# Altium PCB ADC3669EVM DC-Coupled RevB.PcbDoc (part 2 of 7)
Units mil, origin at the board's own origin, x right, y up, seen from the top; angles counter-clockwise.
Board outline 5000 x 2716.54 mil, 12 copper layers (Top Layer, L2 GND, L3 SIG, L4 GND, L5 PWR, L6 GND, L7 GND, L8 PWR, L9 GND, L10 PWR, L11 GND, Bottom Layer), stack 61 mil thick; 546 components, 341 nets, 2088 pads, 1256 vias.
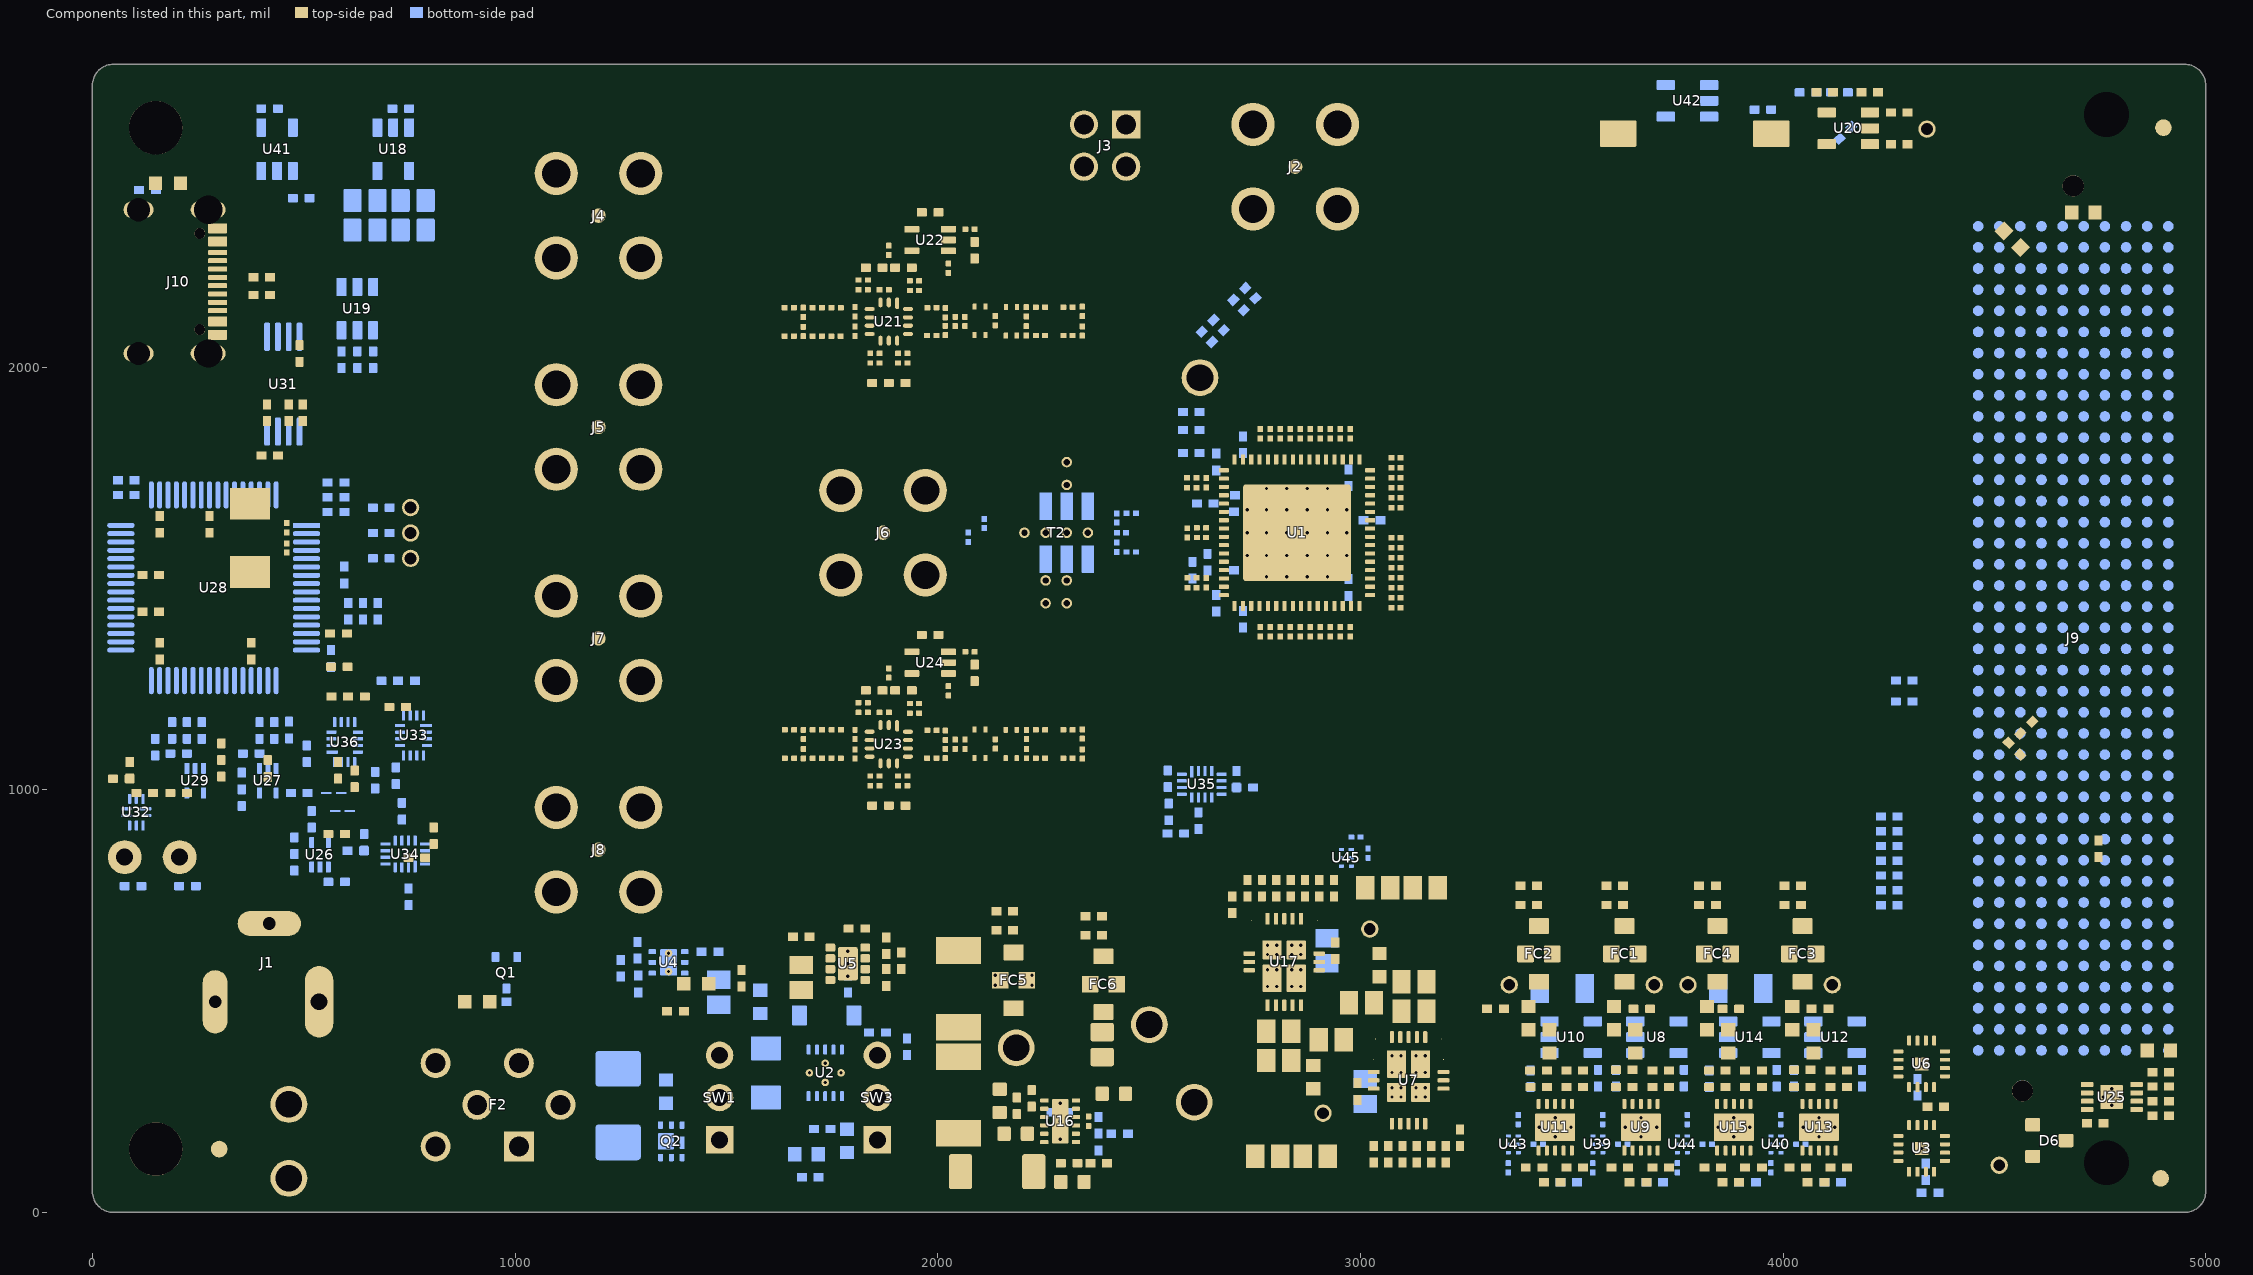
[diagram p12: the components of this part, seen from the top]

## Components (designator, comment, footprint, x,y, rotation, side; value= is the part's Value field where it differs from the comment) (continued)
R220 "ERJ-2GE0R00X" 0402L#2 188.64,1140.31 r270 bottom value="0 Ω"
R221 "ERJ-H2RF1000X" 0402L#2 148.64,1100.94 r90 bottom value="100 Ω"
R222 "ERJ-2GE0R00X" 0402L#1 138.45,1421.08 r0 top value="0 Ω"
R224 "ERJ-2RKF10R0X" 0402L#1 582.21,1369.71 r0 top value="10 Ω"
R225 "ERJ-2RKF1001X" 0402L#1 130.34,2419.03 r0 bottom value="1 kΩ"
R227 "ERJ-2RKF10R0X" 0402L#1 400.5,2212.28 r0 top value="10 Ω"
R229 "ERJ-2RKF10R0X" 0402L#1 400.5,2170.78 r0 top value="10 Ω"
R240 "ERA-2ARB123X" 0402L#1 595.94,1508.27 r90 bottom value="12 kΩ"
R241 "ERJ-2RKF1002X" 0402L#1 464.48,1892.15 r90 top value="10 kΩ"
R242 "ERJ-2RKF1002X" 0402L#1 413.3,1892.15 r90 top value="10 kΩ"
R243 "ERJ-2RKF1002X" 0402L#1 498.07,1892.15 r90 top value="10 kΩ"
R244 "ERJ-2RKF2201X" 0402L#1 419.87,1791.02 r0 top value="2.2 kΩ"
R245 "ERJ-H2RF4701X" 0402L#2 225.01,772.13 r0 bottom value="4.7 kΩ"
R246 "ERJ-H2RF4701X" 0402L#2 96.14,772.13 r0 bottom value="4.7 kΩ"
R247 "ERJ-2GEJ472X" 0402L#1 88.25,1045.83 r90 top value="4.7 kΩ"
R248 "ERJ-2GE0R00X" 0402L#2 68.57,1026.14 r0 top value="0 Ω"
R249 "ERJ-H2RF4701X" 0402L#2 683.31,1607.55 r180 bottom value="4.7 kΩ"
R250 "ERJ-H2RF4701X" 0402L#2 4133.43,2650 r0 bottom value="4.7 kΩ"
R251 "ERJ-H2RF4701X" 0402L#2 683.31,1547.55 r0 bottom value="4.7 kΩ"
R252 "ERJ-H2RF4701X" 0402L#2 683.31,1667.55 r0 bottom value="4.7 kΩ"
R253 "ERJ-H2RF4701X" 0402L#2 4059.06,2650 r0 bottom value="4.7 kΩ"
R254 "ERJ-H2RF4701X" 0402L#2 1927.43,392.06 r90 bottom value="4.7 kΩ"
R255 "ERJ-2GEJ472X" 0402L#1 743.15,1257.76 r0 bottom value="4.7 kΩ"
R256 "ERJ-2GE0R00X" 0402L#2 703.78,1257.76 r0 bottom value="0 Ω"
R257 "ERJ-H2RF4701X" 0402L#2 2706.9,1024.95 r90 bottom value="4.7 kΩ"
R258 "ERJ-2GEJ472X" 0402L#1 623.26,855.94 r180 bottom value="4.7 kΩ"
R259 "ERA-2AED102X" 0402L#2 732.31,949.25 r90 bottom value="1 kΩ"
R260 "ERJ-H2RF4701X" 0402L#2 2563.35,896.64 r0 bottom value="4.7 kΩ"
R261 "ERJ-H2RF4701X" 0402L#2 2616.78,926.95 r90 bottom value="4.7 kΩ"
R262 "ERJ-2GE0R00X" 0402L#2 642.94,875.63 r270 bottom value="0 Ω"
R263 "ERJ-2GE0R00X" 0402L#2 2726.59,1005.26 r180 bottom value="0 Ω"
R264 "ERJ-2GEJ472X" 0402L#1 585.51,1220.56 r180 top value="4.7 kΩ"
R266 "ERA-2AED102X" 0402L#2 718,1033.31 r270 bottom value="1 kΩ"
R267 "ERJ-2GE0R00X" 0402L#2 624.88,1220.56 r180 top value="0 Ω"
R272 "ERJ-1GN0R00C" 0201#2 3820.6,161.38 r0 bottom value="0 Ω"
R273 "ERA-2AEB202X" 0402L#2 589.45,2017.56 r270 bottom value="2 kΩ"
R274 "ERA-2AEB202X" 0402L#2 626.85,2017.56 r270 bottom value="2 kΩ"
R275 "ERA-2AEB202X" 0402L#2 664.25,2017.56 r270 bottom value="2 kΩ"
SW1 "cmp00353" 450301014042 1484,271.9 r270 top
SW2 "FSMSM" FSMSM 3790.75,2552.4 r180 top
SW3 "450301014042" 450301014042 1857.15,271.9 r270 top
T2 "TCM2-33WX+" "DB1627 - Vias 1,2,5" 2305.23,1608.27 r0 bottom
TP1 "5010" Keystone5010 465,255.74 r90 top
TP2 "cmp00041" Keystone5011 2606.78,260.81 r90 top
TP3 "5125" Keystone5125 465,80.74 r90 top
TP4 "cmp00043" Keystone5013 2620.51,1975 r90 top
TP5 "cmp00058" Keystone5117 206.45,840.61 r90 top
TP6 "cmp00058" Keystone5117 76.45,840.61 r90 top
TP8 "5127" Keystone5127 2500.85,444.63 r90 top
TP9 "5012" Keystone5012 2185.67,389.33 r90 top
U1 "ADC3669RTD" RTD0064L 2850,1608.27 r270 top locked
U2 "TPS259261DRC" DRC0010J 1733.87,330.21 r90 bottom
U3 "ADS1119IRTER" RTE0016D 4327.8,151.44 r270 top
U4 "TPS7A2501DRVR" DRV0006A 1363.17,591.58 r0 bottom
U5 "TPS82140SILR" SIL0008D 1787.18,588.32 r0 top
U6 "ADS1119IRTER" RTE0016D 4327.8,351.44 r270 top
U7 "TPSM82913RDUR" RDU0028A 3113.94,312.61 r180 top
U8 "INA180B1IDBVR" DBV0005A 3701.57,414.63 r0 bottom
U9 "TPS7A9401DSC" DSC0010 3663.77,201.64 r90 top
U10 "INA180B1IDBVR" DBV0005A 3498.64,414.63 r0 bottom
U11 "TPS7A9401DSC" DSC0010 3460.84,201.64 r90 top
U12 "INA180B1IDBVR" DBV0005A 4122.88,414.63 r0 bottom
U13 "TPS7A9401DSC" DSC0010 4085.08,201.64 r90 top
U14 "INA180B1IDBVR" DBV0005A 3921.32,414.63 r0 bottom
U15 "TPS7A9401DSC" DSC0010 3883.53,201.64 r90 top
U16 "LM27762DSS" DSS0012B 2289.55,215.75 r0 top
U17 "TPSM82913RDUR" RDU0028A 2819.69,592.56 r0 top
U18 "TPS70950DBV" DBV0005A 711.75,2515.35 r270 bottom
U19 "LM3880MFE-1AD" DBV0006A 626.85,2138.42 r270 bottom
U20 "TPS3125J18DBVR" DBV0005A 4154.29,2565 r180 top
U21 "LMH5401IRMSR" RMS0014A 1884.25,2107.84 r270 top
U22 "OPA376AIDCKR" DCK0005A 1981.93,2300.71 r180 top
U23 "LMH5401IRMSR" RMS0014A 1884.25,1107.84 r270 top
U24 "OPA376AIDCKR" DCK0005A 1981.93,1300.71 r180 top
U25 "24LC64FT-I/MNY" TDFN8 4777.42,273.14 r180 top
U26 "SN74AUP1G126DRL" DRL0005A 538.52,846.24 r90 bottom
U27 "SN74LVC1G126DRL" DRL0005A 415.07,1021.5 r270 bottom
U28 "FT4232HL-REEL" LQFP64-MFG 287.11,1477.98 r180 bottom locked
U29 "SN74LVC1G125DRL" DRL0005A 243.33,1021.5 r270 bottom
U31 "93LC46B-I/ST" TSSOP-8 451.68,1959.67 r90 bottom
U32 "TMUX154ERSW" RSW0010A 104,947 r180 bottom
U33 "SN74CBTLV3257RSV" RSV0016A 759.87,1128.5 r180 bottom
U34 "SN74AVC4T774RSV" RSV0016A 740.19,848.07 r90 bottom
U35 "SN74AVC4T774RSV" RSV0016A 2624.66,1013.14 r270 bottom
U36 "SN74AVC4T774RSV" RSV0016A 596.88,1112.76 r0 bottom
U39 "SN74AUP1G08DRY" DRY0006A 3561.73,161.29 r180 bottom
U40 "SN74AUP1G08DRY" DRY0006A 3983.04,161.29 r180 bottom
U41 "TPS3847108DBVR" DBV0005A 436.95,2515.35 r90 bottom
U42 "SN74LVC1G04DBV" DBV0005A 3773.82,2630 r180 bottom
U43 "SN74AUP1G08DRY" DRY0006A 3361.73,161.29 r180 bottom
U44 "SN74AUP1G08DRY" DRY0006A 3761.73,161.29 r180 bottom
U45 "SN74AUP1G08DRY" DRY0006A 2966.68,839.08 r180 bottom
Y1 "ABM3-12.000MHZ-D2Y-T" XTAL_ABM3 372.69,1596.09 r270 top
ZZ1 "This Assembly Note is for PCB labels only. Put sticker on top of board." AssemblyNoteLabel 382.34,5272.5 r0 top
ZZ2 "These assemblies are ESD sensitive, ESD precautions shall be observed." AssemblyNote 382.34,5422.11 r0 top
ZZ3 "These assemblies must be clean and free from flux and all contaminants. Use of no clean flux is not acceptable." AssemblyNote 382.34,5571.73 r0 top
ZZ4 "These assemblies must comply with workmanship standards IPC-A-610 Class 2, unless otherwise specified." AssemblyNote 382.34,5720.36 r0 top

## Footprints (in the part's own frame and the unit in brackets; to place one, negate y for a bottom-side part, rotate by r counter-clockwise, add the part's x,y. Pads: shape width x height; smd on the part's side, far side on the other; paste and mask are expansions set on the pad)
0201#1 [mm] "Data from Kemet datasheet CC101_COM dated 7/28/11"
  rect 0.36x0.32 smd mask+0.048: 1(-0.28,0) 2(0.28,0)
  body extent -0.31,-0.16 0.31,0.16, height 0.26
0201#2 [mm] "Data from Kemet datasheet CC101_COM dated 7/28/11"
  rrect20% 0.36x0.32 smd mask+0.051: 1(-0.28,0) 2(0.28,0)
  body extent -0.3,-0.15 0.3,0.15, height 0.23
0201_cap#1 [mm] "Data from Kemet datasheet CC101_COM dated 7/28/11"
  rrect20% 0.36x0.32 smd mask+0.051: 1(-0.28,0) 2(0.28,0)
  body extent -0.31,-0.16 0.31,0.16, height 0.26
0201_cap#2 [mm] "Data from Kemet datasheet CC101_COM dated 7/28/11"
  rect 0.36x0.32 smd mask+0.048: 1(-0.28,0) 2(0.28,0)
  body extent -0.31,-0.16 0.31,0.16, height 0.26
0402L#1 [mm] "0402 from SM-752 data"
  rect 0.6x0.5 smd: 1(-0.5,0) 2(0.5,0)
  body extent -0.55,-0.3 0.55,0.3, height 0.6
0402L#2 [mm] "0402 from SM-752 data"
  rrect20% 0.6x0.5 smd mask+0.051: 1(-0.5,0) 2(0.5,0)
  body extent -0.55,-0.3 0.55,0.3, height 0.6
0402L_cap#1 [mm] "0402 from SM-752 data"
  rect 0.6x0.5 smd: 1(-0.5,0) 2(0.5,0)
  body extent -0.55,-0.3 0.55,0.3, height 0.6
0402L_cap#2 [mm] "0402 from SM-752 data"
  rrect20% 0.6x0.5 smd mask+0.051: 1(-0.5,0) 2(0.5,0)
  body extent -0.55,-0.3 0.55,0.3, height 0.6
0603L [mm] "0603 from SM-752 data"
  rect 0.8x0.85 smd: 1(-0.7,0) 2(0.7,0)
  silkscreen extent -0.07,-0.33 0.07,0.33, body extent -0.87,-0.47 0.87,0.47, height 1
0603L_cap#1 [mm] "0603 from SM-752 data"
  rect 0.8x0.85 smd: 1(-0.7,0) 2(0.7,0)
  silkscreen extent -0.07,-0.33 0.07,0.33, body extent -0.87,-0.47 0.87,0.47, height 1
0603L_cap#2 [mm] "0603 from SM-752 data"
  rrect20% 0.8x0.85 smd: 1(-0.7,0) 2(0.7,0)
  silkscreen extent -0.07,-0.33 0.07,0.33, body extent -0.87,-0.47 0.87,0.47, height 1
0805L [mm] "0805 from SM-752 data"
  rrect20% 1.1x1.4 smd: 1(-0.75,0) 2(0.75,0)
  body extent -1.1,-0.72 1.1,0.72, height 1.45
0805L_cap#1 [mm] "0805 from SM-752 data"
  rect 1.1x1.4 smd: 1(-0.75,0) 2(0.75,0)
  body extent -1.1,-0.72 1.1,0.72, height 1.45
0805L_cap#2 [mm] "0805 from SM-752 data"
  rrect20% 1.1x1.4 smd: 1(-0.75,0) 2(0.75,0)
  body extent -1.1,-0.72 1.1,0.72, height 1.45
1206L [mm] "1206 from SM-752 data"
  rect 1.1x1.75 smd: 1(-1.35,0) 2(1.35,0)
  silkscreen extent -0.4,-0.77 0.4,0.77, body extent -1.7,-0.9 1.7,0.9, height 1.35
2010 [mm] "Chip Capacitor, Body 5.08x2.54mm, IPC Medium Density"
  rect 1.6x2.7 smd: 1(-2.3,0) 2(2.3,0)
  body extent -2.73,-1.45 2.73,1.45, height 1.66
026011C [mm] "CoilCraft 026011C Series Inductors"
  rrect20% 0.25x0.36 smd mask+0.05: 1(-0.33,0) 2(0.33,0)
  body extent -0.38,-0.16 0.38,0.17, height 0.56
450301014042 [mm]
  round 1.65 hole 1.016: 1(0,0) 2(-2.54,0)
  rect 1.65x1.65 hole 1.016: 3(2.54,0)
  silkscreen extent -4.25,-1.3 4.25,1.6, body extent -4.98,-1.25 5.02,1.25, height 5.9
AssemblyNote [mil] "Assembly Note"
AssemblyNoteLabel [mil] "Assembly Note for PCB Labels"
CE_Mark_5mm [mil] "Minimum text height for CE Mark"
  silkscreen extent -138,-98 138,98
"DB1627 - Vias 1,2,5" [mm]
  rrect10% 0.76x1.65 smd: 1(-1.27,1.59) 2(0,1.59) 3(1.27,1.59) 4(1.27,-1.59) 5(0,-1.59) 6(-1.27,-1.59)
  round 0.635 hole 0.381 mask+0.05: 5(-2.54,0) 5(-1.27,0) 5(-1.27,2.87) 5(-1.27,4.242) 5(0,0) 5(0,-4.242) 5(0,-2.87) 5(0,2.87) 5(0,4.242) 5(1.27,0)
  silkscreen extent -1.91,-1.91 1.91,3.09, body extent -1.91,-1.91 1.9,1.9, height 3.13
DBV0005A [mm] "SOT23, 5-Leads, Body 2.9x1.6mm, Pitch 0.95mm, Lead Span 2.8mm, IPC High Density"
  rrect18% 1.1x0.6 smd mask+0.07: 1(-1.3,0.95) 2(-1.3,0) 3(-1.3,-0.95) 4(1.3,-0.95) 5(1.3,0.95)
  silkscreen extent -0.35,-1.55 0.35,1.55, body extent -1.42,-1.46 1.42,1.46, height 1.09
DBV0006A [mm] "SOT23, 6-Leads, Body 2.9x1.6mm, Pitch 0.95mm, Lead Span 2.8mm, IPC High Density"
  rrect18% 1.1x0.6 smd mask+0.07: 1(-1.3,0.95) 2(-1.3,0) 3(-1.3,-0.95) 4(1.3,-0.95) 5(1.3,0) 6(1.3,0.95)
  silkscreen extent -0.35,-1.55 0.35,1.55, body extent -1.5,-1.5 1.5,1.5, height 1.3
DCK0005A [mm] "SOT353, 5-Leads, Body 2x1.3mm, Pitch 0.65mm, Lead Span 2.1mm, IPC High Density"
  rrect25% 0.9x0.4 smd mask+0.05: 1(-1.1,0.65) 2(-1.1,0) 3(-1.1,-0.65) 4(1.1,-0.65) 5(1.1,0.65)
  silkscreen extent -0.25,-1.1 0.25,1.1, body extent -1.14,-1 1.14,1, height 0.95
DQK0006C [mm] "WSON"
  rrect12% 0.9x0.86 on Bottom Paste: 0(0,0.325)
  rrect34% 0.7x0.29 on Bottom Paste: 0(0.095,-0.65)
  rrect33% 0.45x0.3 smd: 1(-0.975,0.65) 2(-0.975,0) 3(-0.975,-0.65) 4(0.975,-0.65) 5(0.975,0) 6(0.975,0.65)
  rrect33% 0.75x0.3 smd paste-0.15: 7(0.095,-0.65)
  rrect11% 1x0.95 smd paste-0.5: 8(0,0.325)
  silkscreen extent -1.15,-1.15 1.15,1.15, body extent -1,-1 1,1, height 0.75
DRC0010J [mm] "VSON-10"
  rrect42% 0.6x0.24 smd mask+0.07: 1(-1.4,1) 2(-1.4,0.5) 3(-1.4,0) 4(-1.4,-0.5) 5(-1.4,-1) 6(1.4,-1) 7(1.4,-0.5) 8(1.4,0) 9(1.4,0.5) 10(1.4,1)
  round 0.454 hole 0.2 mask+0.05: 11(-0.575,0) 11(0,-0.95) 11(0,0.95) 11(0.575,0)
  round 0.025 smd mask+0.07: 11(0,0)
  Top Layer region: -0.375,-1.65 -0.375,-1.2 -0.775,-1.2 -0.794,-1.196 -0.81,-1.185 -0.821,-1.169 -0.825,-1.15 -0.825,-1.15 -0.825,1.15 -0.821,1.169 -0.81,1.185 -0.794,1.196 -0.775,1.2 -0.775,1.2 -0.375,1.2 -0.375,1.65 -0.371,1.669 -0.36,1.685 -0.344,1.696 -0.325,1.7 -0.325,1.7 -0.325,1.7 -0.175,1.7 -0.175,1.7 -0.156,1.696 -0.14,1.685 -0.129,1.669 -0.125,1.65 -0.125,1.65 -0.125,1.2 0.125,1.2 0.125,1.65 0.129,1.669 0.14,1.685 0.156,1.696 0.175,1.7 0.175,1.7 0.175,1.7 0.325,1.7 0.325,1.7 0.344,1.696 0.36,1.685 0.371,1.669 0.375,1.65 0.375,1.65 0.375,1.2 0.775,1.2 0.794,1.196 0.81,1.185 0.821,1.169 0.825,1.15 0.825,1.15 0.825,-1.15 0.821,-1.169 0.81,-1.185 0.794,-1.196 0.775,-1.2 0.775,-1.2 0.375,-1.2 0.375,-1.65 0.371,-1.669 0.36,-1.685 0.344,-1.696 0.325,-1.7 0.325,-1.7 0.175,-1.7 0.156,-1.696 0.14,-1.685 0.129,-1.669 0.125,-1.65 0.125,-1.65 0.125,-1.2 -0.125,-1.2 -0.125,-1.65 -0.129,-1.669 -0.14,-1.685 -0.156,-1.696 -0.175,-1.7 -0.175,-1.7 -0.325,-1.7 -0.344,-1.696 -0.36,-1.685 -0.371,-1.669 -0.375,-1.65
  silkscreen extent -1.97,0.95 -1.84,1.08, body extent -1.5,-1.5 1.5,1.5, height 1
DRL0005A [mm] "SOTFL, 5-Flat Leads, Body 1.2x1.6x0.6mm, Pitch 0.5mm, TI recommended"
  rrect33% 0.67x0.3 smd mask+0.05: 1(-0.74,0.5) 2(-0.74,0) 3(-0.74,-0.5) 4(0.74,-0.5) 5(0.74,0.5)
  silkscreen extent -0.9,-0.95 0.5,0.95, body extent -0.8,-0.8 0.8,0.8, height 0.6
DRV0006A [mm] "SON, 6-Leads, Body 2x2mm, Pitch 0.65mm, Thermal Pad 1.6x1mm, TI Recommended"
  rrect33% 0.45x0.3 smd mask+0.07: 1(-0.975,0.65) 2(-0.975,0) 3(-0.975,-0.65) 4(0.975,-0.65) 5(0.975,0) 6(0.975,0.65)
  round 0.454 hole 0.2 mask+0: 7(0,-0.55) 7(0,0.55)
  rrect14% 1x0.7 on Bottom Paste: 7(0,-0.45) 7(0,0.45)
  rrect10% 1x1.6 smd paste-0.5 mask+0.07: 7(0,0)
  silkscreen extent -1.05,-1.2 1.05,1.2, body extent -1,-1 1,1, height 0.75
DRY0006A [mm]
  rrect20% 0.35x0.2 smd mask+0.05: 1(-0.298,0.5)
  rrect20% 0.3x0.2 smd mask+0.05: 2(-0.303,0) 3(-0.303,-0.5) 4(0.303,-0.5) 5(0.303,0) 6(0.303,0.5)
  silkscreen extent -0.76,0.64 -0.71,0.69, body extent -0.5,-0.72 0.5,0.72, height 0.6
DSC0010 [mm]
  rrect50% 0.6x0.24 smd paste+0 mask+0.07: 1(-1.4,1) 2(-1.4,0.5) 3(-1.4,0) 4(-1.4,-0.5) 5(-1.4,-1) 6(1.4,-1) 7(1.4,-0.5) 8(1.4,0) 9(1.4,0.5) 10(1.4,1)
  round 0.454 hole 0.2 mask+0.05: 11(-0.575,0) 11(0,0.95) 11(0,-0.95) 11(0.575,0)
  rrect6% 1.65x2.4 smd paste-1000 mask+0: 11(0,0)
  silkscreen extent -1.93,-1.55 1.55,1.55, body extent -1.8,-1.8 1.8,1.8, height 0.25
DSS0012B [mm] "WSON-10"
  rrect40% 0.5x0.25 smd mask+0.05: 1(-0.95,1.25) 2(-0.95,0.75) 3(-0.95,0.25) 4(-0.95,-0.25) 5(-0.95,-0.75) 6(-0.95,-1.25) 7(0.95,-1.25) 8(0.95,-0.75) 9(0.95,-0.25) 10(0.95,0.25) 11(0.95,0.75) 12(0.95,1.25)
  round 0.454 hole 0.2 mask+0.05: 13(0,-1.075) 13(0,1.075) 13(0,0)
  rrect11% 1x2.65 smd paste-0.5 mask+0.05: 13(0,0)
  silkscreen extent -1.3,1.63 -1.24,1.68, body extent -1,-1.5 1,1.5, height 0.8
ESD_Overlay_Medium [mil]
  silkscreen extent -127,-109 125,110
FCC_disclaimer_stacked [mil]
FDL_Small [mil]
  silkscreen extent -54,-32 54,73
Fiducial10-20#1 [mm]
  round 1 smd mask+0.5: 1(101.6,-5.08)
Fiducial10-20#2 [mm]
  round 1 smd mask+0.5: 1(0,0)
Fiducial10-20#3 [mm]
  round 1 smd mask+0.5: 1(0,-1.27)
FIL_BNX002-11 [mm]
  rect 1.8x1.8 hole 1.2: 1(2.5,2.5)
  round 1.8 hole 1.2: 2(2.5,-2.5) 3(-2.5,2.5) 4(-2.5,-2.5) 4(0,0) 4(5,0)
  silkscreen extent -6,-5.5 6,6.35, body extent -6,-5.5 6,5.5, height 13
FP-2116-440-AL_STANDOFF_HEX_1-4-MFG [mm]
  round 3.2 hole 3.2 unplated paste-2539.97 mask+0: ""(0,0)
  body extent -3.66,-3.18 3.66,3.18, height 31.88
FP-132134-15_CONN_SMA_JACK-MFG [mm]
  round 0.864 smd paste+0 mask+0: 1(0,0)
  round 2.6 hole 1.7 paste-2539.97 mask+0: 2(-2.54,2.54) 3(2.54,2.54) 4(-2.54,-2.54) 5(2.54,-2.54)
  silkscreen extent -3.6,-3.6 3.6,3.6, body extent -3.94,-3.94 3.94,3.94, height 0.25
FP-USB4105-GF-A_CONN_USB_9MM58_7MM53-MFG [mm]
  rrect100% 1x2.1 hole 1.7 slot 0.6 at 0 deg paste-2539.97 mask+0: 1(-4.32,3.015) 2(4.32,3.015)
  rrect100% 1x1.8 hole 1.4 slot 0.6 at 0 deg paste-2539.97 mask+0: 3(-4.32,-1.165) 4(4.32,-1.165)
  rrect17% 0.6x1.15 smd paste+0 mask+0: A1(-3.2,3.59) A4(-2.4,3.59) B1(3.2,3.59) B4(2.4,3.59)
  rrect33% 0.3x1.15 smd paste+0 mask+0: A5(-1.25,3.59) A6(-0.25,3.59) A7(0.25,3.59) A8(1.25,3.59) B5(1.75,3.59) B6(0.75,3.59) B7(-0.75,3.59) B8(-1.75,3.59)
  round 0.65 hole 0.65 unplated paste-2539.97 mask+0: ""(-2.89,2.515) ""(2.89,2.515)
  silkscreen extent -4.86,0.11 4.86,4.84, body extent -4.96,-3.94 4.96,4.27, height 0.25
FSMSM [mm]
  rrect10% 2.2x1.6 smd: 1(-4.6,0) 2(4.6,0)
  body extent -4.98,-1.75 4.98,1.75, height 4.4
Keystone5010 [mil] "Keystone Multipurpose loops"
  round 87 hole 63: 1(0,0)
  silkscreen extent -70,-70 70,70, body extent -63,-63 62,62, height 319
Keystone5011 [mil] "Keystone Multipurpose loops"
  round 87 hole 63: 1(0,0)
  silkscreen extent -70,-70 70,70, body extent -63,-63 63,62, height 319
Keystone5012 [mil] "Keystone Multipurpose loops"
  round 87 hole 63: 1(0,0)
  silkscreen extent -70,-70 70,70, body extent -63,-63 63,62, height 319
Keystone5013 [mil] "Keystone Multipurpose loops"
  round 87 hole 63: 1(0,0)
  silkscreen extent -70,-70 70,70, body extent -63,-63 63,62, height 319
Keystone5117 [mil] "For Keystone 500x miniature loop terminals"
  round 80 hole 40: 1(0,0)
  silkscreen extent -52,-52 52,52, body extent -49,-49 49,49, height 182
Keystone5125 [mil] "Keystone Multipurpose loops"
  round 87 hole 63: 1(0,0)
  silkscreen extent -70,-70 70,70, body extent -63,-63 63,62, height 319
Keystone5127 [mil] "Keystone Multipurpose loops"
  round 87 hole 63: 1(0,0)
  silkscreen extent -70,-70 70,70, body extent -63,-63 63,62, height 319
Label_650x200 [mil] "Thermal Transfer Label"
  round 1 on Mech13: 0(0,0)
  silkscreen extent -325,-100 325,100, body extent -325,-100 325,100, height 1
LED_LTST-C190-Green [mm] "Lite-On"
  rect 0.8x0.8 smd: 1(-0.75,0) 2(0.75,0)
  silkscreen extent -1.1,-0.8 1.8,0.8, body extent -0.85,-0.45 0.85,0.45, height 0.91
LQFP64-MFG [mm]
  rrect33% 1.65x0.3 smd paste+0 mask+0.05: 1(-5.575,3.75)
  rrect100% 1.65x0.3 smd paste+0 mask+0.05: 2(-5.575,3.25) 3(-5.575,2.75) 4(-5.575,2.25) 5(-5.575,1.75) 6(-5.575,1.25) 7(-5.575,0.75) 8(-5.575,0.25) 9(-5.575,-0.25) 10(-5.575,-0.75) 11(-5.575,-1.25) 12(-5.575,-1.75) 13(-5.575,-2.25) 14(-5.575,-2.75) 15(-5.575,-3.25) 16(-5.575,-3.75) 33(5.575,-3.75) 34(5.575,-3.25) 35(5.575,-2.75) 36(5.575,-2.25) 37(5.575,-1.75) 38(5.575,-1.25) 39(5.575,-0.75) 40(5.575,-0.25) 41(5.575,0.25) 42(5.575,0.75) 43(5.575,1.25) 44(5.575,1.75) 45(5.575,2.25) 46(5.575,2.75) 47(5.575,3.25) 48(5.575,3.75)
  rrect100% 0.3x1.65 smd paste+0 mask+0.05: 17(-3.75,-5.575) 18(-3.25,-5.575) 19(-2.75,-5.575) 20(-2.25,-5.575) 21(-1.75,-5.575) 22(-1.25,-5.575) 23(-0.75,-5.575) 24(-0.25,-5.575) 25(0.25,-5.575) 26(0.75,-5.575) 27(1.25,-5.575) 28(1.75,-5.575) 29(2.25,-5.575) 30(2.75,-5.575) 31(3.25,-5.575) 32(3.75,-5.575) 49(3.75,5.575) 50(3.25,5.575) 51(2.75,5.575) 52(2.25,5.575) 53(1.75,5.575) 54(1.25,5.575) 55(0.75,5.575) 56(0.25,5.575) 57(-0.25,5.575) 58(-0.75,5.575) 59(-1.25,5.575) 60(-1.75,5.575) 61(-2.25,5.575) 62(-2.75,5.575) 63(-3.25,5.575) 64(-3.75,5.575)
  silkscreen extent -7.13,-5.05 5.05,5.05, body extent -6,-6 6,6, height 1.6
Net-Tie_5milWide_60milLong [mil] "5mil net tie, no solder mask opening, no solder paste"
  rect 25x5 smd paste-5 mask-5: 1(-17.5,0) 2(17.5,0)
  Top Layer region: -10,2.5 10,2.5 10,-2.5 -10,-2.5
NFM31PC#1 [mm]
  rrect10% 0.95x1.2 smd paste+0: 1(-1.675,0) 3(1.675,0)
  rrect10% 1x1 smd paste+0: 2(0,0.8) 2(0,-0.8)
  body extent -1.7,-0.9 1.7,0.9, height 1.5
NFM31PC#2 [mm]
  rrect10% 0.95x1.2 smd paste+0: 1(-1.675,0) 3(1.675,0)
  round 0.2 / inner round 0.454 / far side round 0.454 hole 0.2 mask+0.05: 2(-0.305,1.105) 2(-0.305,-1.105) 2(0.305,1.105) 2(0.305,-1.105)
  rrect10% 1x1 smd paste+0: 2(0,0.8) 2(0,-0.8)
  body extent -1.7,-0.9 1.7,0.9, height 1.5
PBC02DAAN [mm] "Header, 2.54mm, 2x2, TH"
  rect 1.7x1.7 hole 1.2: 1(-1.27,1.27)
  round 1.7 hole 1.2: 2(1.27,1.27) 3(-1.27,-1.27) 4(1.27,-1.27)
  silkscreen extent -2.61,-2.8 2.61,3.2, body extent -2.61,-2.8 2.61,2.8, height 8.58
ProbePoint_TH_40mil [mil]
  round 41 hole 28: 1(0,0)
RAPC722X [mm] "Conn_DC Jack"
  oval 1.7x4.3 hole 1.01 slot 3.56 at 90 deg: 1(14.194,0)
  oval 1.5x3.8 hole 0.76 slot 3.05 at 90 deg: 2(7.946,0)
  oval 3.8x1.5 hole 0.76 slot 3.05 at 0 deg: 3(11.197,-4.7)
  silkscreen extent 0.2,-4.57 14.93,4.57, body extent 0.58,-4.97 15.06,4.56, height 10.92
RDU0028A [mm]
  round 0.025 smd mask+0.05: 1(-1.987,2.487) 2(-2.1,1.25) 6(-2.1,-1.25) 7(-1.987,-2.488) 13(1.987,-2.488) 14(2.1,-1.25) 18(2.1,1.25) 19(1.988,2.488)
  rrect40% 0.7x0.25 smd paste+0 mask+0.05: 3(-2.1,0.5) 4(-2.1,0) 5(-2.1,-0.5) 15(2.1,-0.5) 16(2.1,0) 17(2.1,0.5)
  rrect40% 0.25x0.7 smd paste+0 mask+0.05: 8(-1,-2.6) 9(-0.5,-2.6) 10(0,-2.6) 11(0.5,-2.6) 12(1,-2.6) 20(1,2.6) 21(0.5,2.6) 22(0,2.6) 23(-0.5,2.6) 24(-1,2.6)
  round 0.454 hole 0.2 mask+0.102: 25(-1,1) 25(-1,0.45) 25(-0.45,1) 25(-0.45,0.45) 26(-1,-0.475) 26(-1,-1.475) 26(-0.45,-0.475) 26(-0.45,-1.475) 27(0.45,-0.475) 27(0.45,-1.475) 27(1,-0.475) 27(1,-1.475) 28(0.45,1) 28(0.45,0.45) 28(1,1) 28(1,0.45)
  rrect9% 1.15x1.15 smd paste-1000 mask+0.05: 25(-0.725,0.725) 28(0.725,0.725)
  rrect9% 1.15x1.65 smd paste-1000 mask+0.05: 26(-0.725,-0.975) 27(0.725,-0.975)
  Top Layer region: 2.4,-1.625 1.8,-1.625 1.775,-1.618 1.757,-1.6 1.75,-1.575 1.75,-1.575 1.75,-0.925 1.754,-0.906 1.765,-0.89 1.781,-0.879 1.8,-0.875 1.8,-0.875 2.4,-0.875 2.419,-0.879 2.435,-0.89 2.446,-0.906 2.45,-0.925 2.45,-0.925 2.45,-1.075 2.443,-1.1 2.425,-1.118 2.4,-1.125 2.4,-1.125 2.225,-1.125 2.187,-1.133 2.154,-1.154 2.133,-1.187 2.125,-1.225 2.125,-1.225 2.125,-1.275 2.138,-1.325 2.175,-1.362 2.225,-1.375 2.225,-1.375 2.4,-1.375 2.419,-1.379 2.435,-1.39 2.446,-1.406 2.45,-1.425 2.45,-1.425 2.45,-1.575 2.443,-1.6 2.425,-1.618 2.4,-1.625
  Top Layer region: 1.575,-2.95 1.55,-2.943 1.532,-2.925 1.525,-2.9 1.525,-2.9 1.525,-2.075 1.529,-2.056 1.54,-2.04 1.556,-2.029 1.575,-2.025 1.575,-2.025 2.4,-2.025 2.423,-2.033 2.439,-2.051 2.445,-2.075 2.445,-2.075 2.45,-2.225 2.443,-2.25 2.425,-2.268 2.4,-2.275 2.4,-2.275 2.225,-2.275 2.187,-2.283 2.154,-2.304 2.133,-2.337 2.125,-2.375 2.125,-2.375 2.125,-2.575 2.118,-2.6 2.1,-2.618 2.075,-2.625 2.075,-2.625 1.875,-2.625 1.837,-2.633 1.804,-2.654 1.783,-2.687 1.775,-2.725 1.775,-2.725 1.775,-2.9 1.768,-2.925 1.75,-2.943 1.725,-2.95 1.725,-2.95
  Top Layer region: 2.4,0.875 1.8,0.875 1.775,0.882 1.757,0.9 1.75,0.925 1.75,0.925 1.75,1.575 1.754,1.594 1.765,1.61 1.781,1.621 1.8,1.625 1.8,1.625 2.4,1.625 2.419,1.621 2.435,1.61 2.446,1.594 2.45,1.575 2.45,1.575 2.45,1.425 2.443,1.4 2.425,1.382 2.4,1.375 2.4,1.375 2.225,1.375 2.187,1.367 2.154,1.346 2.133,1.313 2.125,1.275 2.125,1.275 2.125,1.225 2.138,1.175 2.175,1.138 2.225,1.125 2.225,1.125 2.4,1.125 2.419,1.121 2.435,1.11 2.446,1.094 2.45,1.075 2.45,1.075 2.45,0.925 2.443,0.9 2.425,0.882 2.4,0.875
  Top Layer region: 1.575,2.95 1.55,2.943 1.532,2.925 1.525,2.9 1.525,2.9 1.525,2.075 1.529,2.056 1.54,2.04 1.556,2.029 1.575,2.025 1.575,2.025 2.4,2.025 2.423,2.033 2.439,2.051 2.445,2.075 2.445,2.075 2.45,2.225 2.443,2.25 2.425,2.268 2.4,2.275 2.4,2.275 2.225,2.275 2.187,2.283 2.154,2.304 2.133,2.337 2.125,2.375 2.125,2.375 2.125,2.575 2.118,2.6 2.1,2.618 2.075,2.625 2.075,2.625 1.875,2.625 1.837,2.633 1.804,2.654 1.783,2.687 1.775,2.725 1.775,2.725 1.775,2.9 1.768,2.925 1.75,2.943 1.725,2.95 1.725,2.95
  Top Layer region: -1.575,2.95 -1.55,2.943 -1.532,2.925 -1.525,2.9 -1.525,2.9 -1.525,2.075 -1.529,2.056 -1.54,2.04 -1.556,2.029 -1.575,2.025 -1.575,2.025 -2.4,2.025 -2.423,2.033 -2.439,2.051 -2.445,2.075 -2.445,2.075 -2.45,2.225 -2.443,2.25 -2.425,2.268 -2.4,2.275 -2.4,2.275 -2.225,2.275 -2.187,2.283 -2.154,2.304 -2.133,2.337 -2.125,2.375 -2.125,2.375 -2.125,2.575 -2.118,2.6 -2.1,2.618 -2.075,2.625 -2.075,2.625 -1.875,2.625 -1.837,2.633 -1.804,2.654 -1.783,2.687 -1.775,2.725 -1.775,2.725 -1.775,2.9 -1.768,2.925 -1.75,2.943 -1.725,2.95 -1.725,2.95
  Top Layer region: -2.4,1.625 -1.8,1.625 -1.781,1.621 -1.765,1.61 -1.754,1.594 -1.75,1.575 -1.75,1.575 -1.75,0.925 -1.754,0.906 -1.765,0.89 -1.781,0.879 -1.8,0.875 -1.8,0.875 -2.4,0.875 -2.419,0.879 -2.435,0.89 -2.446,0.906 -2.45,0.925 -2.45,0.925 -2.45,1.075 -2.443,1.1 -2.425,1.118 -2.4,1.125 -2.4,1.125 -2.225,1.125 -2.187,1.133 -2.154,1.154 -2.133,1.187 -2.125,1.225 -2.125,1.225 -2.125,1.275 -2.138,1.325 -2.175,1.362 -2.225,1.375 -2.225,1.375 -2.4,1.375 -2.419,1.379 -2.435,1.39 -2.446,1.406 -2.45,1.425 -2.45,1.425 -2.45,1.575 -2.443,1.6 -2.425,1.618 -2.4,1.625
  Top Layer region: -2.4,-0.875 -1.8,-0.875 -1.775,-0.882 -1.757,-0.9 -1.75,-0.925 -1.75,-0.925 -1.75,-1.575 -1.754,-1.594 -1.765,-1.61 -1.781,-1.621 -1.8,-1.625 -1.8,-1.625 -2.4,-1.625 -2.419,-1.621 -2.435,-1.61 -2.446,-1.594 -2.45,-1.575 -2.45,-1.575 -2.45,-1.425 -2.443,-1.4 -2.425,-1.382 -2.4,-1.375 -2.4,-1.375 -2.225,-1.375 -2.187,-1.367 -2.154,-1.346 -2.133,-1.313 -2.125,-1.275 -2.125,-1.275 -2.125,-1.225 -2.138,-1.175 -2.175,-1.138 -2.225,-1.125 -2.225,-1.125 -2.4,-1.125 -2.419,-1.121 -2.435,-1.11 -2.446,-1.094 -2.45,-1.075 -2.45,-1.075 -2.45,-0.925 -2.443,-0.9 -2.425,-0.882 -2.4,-0.875
  Top Layer region: -1.575,-2.95 -1.55,-2.943 -1.532,-2.925 -1.525,-2.9 -1.525,-2.9 -1.525,-2.075 -1.529,-2.056 -1.54,-2.04 -1.556,-2.029 -1.575,-2.025 -1.575,-2.025 -2.4,-2.025 -2.423,-2.033 -2.439,-2.051 -2.445,-2.075 -2.445,-2.075 -2.45,-2.225 -2.443,-2.25 -2.425,-2.268 -2.4,-2.275 -2.4,-2.275 -2.225,-2.275 -2.187,-2.283 -2.154,-2.304 -2.133,-2.337 -2.125,-2.375 -2.125,-2.375 -2.125,-2.575 -2.118,-2.6 -2.1,-2.618 -2.075,-2.625 -2.075,-2.625 -1.875,-2.625 -1.837,-2.633 -1.804,-2.654 -1.783,-2.687 -1.775,-2.725 -1.775,-2.725 -1.775,-2.9 -1.768,-2.925 -1.75,-2.943 -1.725,-2.95 -1.725,-2.95
  silkscreen extent -3.2,-3.13 2.63,3.13, body extent -2.55,-3.05 2.55,3.05, height 0.25
RMS0014A [mm] "UQFN-14"
  oval 0.7x0.25 smd mask+0.07: 1(-1.1,0.5)
  oval 0.6x0.25 smd mask+0.07: 2(-1.15,0) 3(-1.15,-0.5) 8(1.15,-0.5) 9(1.15,0) 10(1.15,0.5)
  oval 0.25x0.6 smd mask+0.07: 4(-0.75,-1.15) 5(-0.25,-1.15) 6(0.25,-1.15) 7(0.75,-1.15) 11(0.75,1.15) 12(0.25,1.15) 13(-0.25,1.15) 14(-0.75,1.15)
  silkscreen extent -1.4,-1.4 1.4,1.4, body extent -1.25,-1.25 1.25,1.25, height 0.61
RSV0016A [mm] "QFN, 16-Leads, Body 1.8x2.6mm, Pitch 0.4mm, TI Recommended"
  rrect25% 0.7x0.2 smd mask+0.05: 1(-0.75,0.6)
  rrect25% 0.6x0.2 smd mask+0.05: 2(-0.8,0.2) 3(-0.8,-0.2) 4(-0.8,-0.6) 9(0.8,-0.6) 10(0.8,-0.2) 11(0.8,0.2) 12(0.8,0.6)
  rrect25% 0.2x0.6 smd mask+0.05: 5(-0.6,-1.2) 6(-0.2,-1.2) 7(0.2,-1.2) 8(0.6,-1.2) 13(0.6,1.2) 14(0.2,1.2) 15(-0.2,1.2) 16(-0.6,1.2)
  silkscreen extent -1.08,-1.33 1.08,1.45, body extent -0.85,-1.31 0.85,1.31, height 0.49
RSW0010A [mm]
  rrect50% 0.7x0.2 smd mask+0.05: 1(-0.55,0.2)
  rrect50% 0.6x0.2 smd mask+0.05: 2(-0.6,-0.2) 6(0.6,-0.2) 7(0.6,0.2)
  rrect50% 0.2x0.6 smd mask+0.05: 3(-0.4,-0.8) 4(0,-0.8) 5(0.4,-0.8) 8(0.4,0.8) 9(0,0.8) 10(-0.4,0.8)
  silkscreen extent -0.87,-0.92 0.72,0.92, body extent -0.7,-0.9 0.7,0.9, height 0.49
RTD0064L [mm]
  rrect20% 0.6x0.25 smd mask+0.07: 1(-4.4,3.75) 2(-4.4,3.25) 3(-4.4,2.75) 4(-4.4,2.25) 5(-4.4,1.75) 6(-4.4,1.25) 7(-4.4,0.75) 8(-4.4,0.25) 9(-4.4,-0.25) 10(-4.4,-0.75) 11(-4.4,-1.25) 12(-4.4,-1.75) 13(-4.4,-2.25) 14(-4.4,-2.75) 15(-4.4,-3.25) 16(-4.4,-3.75) 33(4.4,-3.75) 34(4.4,-3.25) 35(4.4,-2.75) 36(4.4,-2.25) 37(4.4,-1.75) 38(4.4,-1.25) 39(4.4,-0.75) 40(4.4,-0.25) 41(4.4,0.25) 42(4.4,0.75) 43(4.4,1.25) 44(4.4,1.75) 45(4.4,2.25) 46(4.4,2.75) 47(4.4,3.25) 48(4.4,3.75)
  rrect20% 0.25x0.6 smd mask+0.07: 17(-3.75,-4.4) 18(-3.25,-4.4) 19(-2.75,-4.4) 20(-2.25,-4.4) 21(-1.75,-4.4) 22(-1.25,-4.4) 23(-0.75,-4.4) 24(-0.25,-4.4) 25(0.25,-4.4) 26(0.75,-4.4) 27(1.25,-4.4) 28(1.75,-4.4) 29(2.25,-4.4) 30(2.75,-4.4) 31(3.25,-4.4) 32(3.75,-4.4) 49(3.75,4.4) 50(3.25,4.4) 51(2.75,4.4) 52(2.25,4.4) 53(1.75,4.4) 54(1.25,4.4) 55(0.75,4.4) 56(0.25,4.4) 57(-0.25,4.4) 58(-0.75,4.4) 59(-1.25,4.4) 60(-1.75,4.4) 61(-2.25,4.4) 62(-2.75,4.4) 63(-3.25,4.4) 64(-3.75,4.4)
  round 0.454 hole 0.2 mask+0.05: 65(-2.654,1.83) 65(-2.654,-0.61) 65(-2.654,0.61) 65(-2.654,-1.83) 65(-1.37,2.983) 65(-1.37,1.83) 65(-1.37,0.61) 65(-1.37,-0.61) 65(-1.37,-1.83) 65(-1.37,-2.983) 65(0,2.983) 65(0,1.83) 65(0,0.61) 65(0,-0.61) 65(0,-1.83) 65(0,-2.983) 65(1.37,2.983) 65(1.37,1.83) 65(1.37,0.61) 65(1.37,-0.61) 65(1.37,-1.83) 65(1.37,-2.983) 65(2.654,1.83) 65(2.654,-0.61) 65(2.654,0.61) 65(2.654,-1.83)
  rrect10% 1.17x1.02 on Top Paste mask+0.05: 65(-2.055,1.22) 65(-2.055,2.44) 65(-2.055,0) 65(-2.055,-2.44) 65(-2.055,-1.22) 65(-0.685,2.44) 65(-0.685,1.22) 65(-0.685,0) 65(-0.685,-1.22) 65(-0.685,-2.44) 65(0.685,2.44) 65(0.685,1.22) 65(0.685,0) 65(0.685,-1.22) 65(0.685,-2.44) 65(2.055,1.22) 65(2.055,2.44) 65(2.055,0) 65(2.055,-2.44) 65(2.055,-1.22)
  rrect5% 5.808x6.466 smd paste-6 mask+0.05: 65(0,0)
  body extent -4.5,-4.5 4.5,4.5, height 1.1
RTE0016D [mm]
  rrect42% 0.6x0.24 smd paste+0 mask+0.07: 1(-1.4,0.75) 2(-1.4,0.25) 3(-1.4,-0.25) 4(-1.4,-0.75) 9(1.4,-0.75) 10(1.4,-0.25) 11(1.4,0.25) 12(1.4,0.75)
  rrect42% 0.24x0.6 smd paste+0 mask+0.07: 5(-0.75,-1.4) 6(-0.25,-1.4) 7(0.25,-1.4) 8(0.75,-1.4) 13(0.75,1.4) 14(0.25,1.4) 15(-0.25,1.4) 16(-0.75,1.4)
  round 0.454 hole 0.2 mask+0.05: 17(0,0)
  rrect6% 0.8x0.8 smd paste-0.04 mask+0: 17(0,0)
  silkscreen extent -2.06,-1.55 1.55,1.55, body extent -1.5,-1.5 1.5,1.5, height 0.8
SAMTEC_ASP-134488-01 [mm]
  round 0.64 smd paste+0.125: A1(24.765,5.715) A2(23.495,5.715) A3(22.225,5.715) A4(20.955,5.715) A5(19.685,5.715) A6(18.415,5.715) A7(17.145,5.715) A8(15.875,5.715) A9(14.605,5.715) A10(13.335,5.715) A11(12.065,5.715) A12(10.795,5.715) A13(9.525,5.715) A14(8.255,5.715) A15(6.985,5.715) A16(5.715,5.715) A17(4.445,5.715) A18(3.175,5.715) A19(1.905,5.715) A20(0.635,5.715) A21(-0.635,5.715) A22(-1.905,5.715) A23(-3.175,5.715) A24(-4.445,5.715) A25(-5.715,5.715) A26(-6.985,5.715) A27(-8.255,5.715) A28(-9.525,5.715) A29(-10.795,5.715) A30(-12.065,5.715) A31(-13.335,5.715) A32(-14.605,5.715) A33(-15.875,5.715) A34(-17.145,5.715) A35(-18.415,5.715) A36(-19.685,5.715) A37(-20.955,5.715) A38(-22.225,5.715) A39(-23.495,5.715) A40(-24.765,5.715) B1(24.765,4.445) B2(23.495,4.445) B3(22.225,4.445) B4(20.955,4.445) B5(19.685,4.445) B6(18.415,4.445) B7(17.145,4.445) B8(15.875,4.445) B9(14.605,4.445) B10(13.335,4.445) B11(12.065,4.445) B12(10.795,4.445) B13(9.525,4.445) B14(8.255,4.445) B15(6.985,4.445) B16(5.715,4.445) B17(4.445,4.445) B18(3.175,4.445) B19(1.905,4.445) B20(0.635,4.445) B21(-0.635,4.445) B22(-1.905,4.445) B23(-3.175,4.445) B24(-4.445,4.445) B25(-5.715,4.445) B26(-6.985,4.445) B27(-8.255,4.445) B28(-9.525,4.445) B29(-10.795,4.445) B30(-12.065,4.445) B31(-13.335,4.445) B32(-14.605,4.445) B33(-15.875,4.445) B34(-17.145,4.445) B35(-18.415,4.445) B36(-19.685,4.445) B37(-20.955,4.445) B38(-22.225,4.445) B39(-23.495,4.445) B40(-24.765,4.445) C1(24.765,3.175) C2(23.495,3.175) C3(22.225,3.175) C4(20.955,3.175) C5(19.685,3.175) C6(18.415,3.175) C7(17.145,3.175) C8(15.875,3.175) C9(14.605,3.175) C10(13.335,3.175) C11(12.065,3.175) C12(10.795,3.175) C13(9.525,3.175) C14(8.255,3.175) C15(6.985,3.175) C16(5.715,3.175) C17(4.445,3.175) C18(3.175,3.175) C19(1.905,3.175) C20(0.635,3.175) C21(-0.635,3.175) C22(-1.905,3.175) C23(-3.175,3.175) C24(-4.445,3.175) C25(-5.715,3.175) C26(-6.985,3.175) C27(-8.255,3.175) C28(-9.525,3.175) C29(-10.795,3.175) C30(-12.065,3.175) C31(-13.335,3.175) C32(-14.605,3.175) C33(-15.875,3.175) C34(-17.145,3.175) C35(-18.415,3.175) C36(-19.685,3.175) C37(-20.955,3.175) C38(-22.225,3.175) C39(-23.495,3.175) C40(-24.765,3.175) D1(24.765,1.905) D2(23.495,1.905) D3(22.225,1.905) D4(20.955,1.905) D5(19.685,1.905) D6(18.415,1.905) D7(17.145,1.905) D8(15.875,1.905) D9(14.605,1.905) D10(13.335,1.905) D11(12.065,1.905) D12(10.795,1.905) D13(9.525,1.905) D14(8.255,1.905) D15(6.985,1.905) D16(5.715,1.905) D17(4.445,1.905) D18(3.175,1.905) D19(1.905,1.905) D20(0.635,1.905) D21(-0.635,1.905) D22(-1.905,1.905) D23(-3.175,1.905) D24(-4.445,1.905) D25(-5.715,1.905) D26(-6.985,1.905) D27(-8.255,1.905) D28(-9.525,1.905) D29(-10.795,1.905) D30(-12.065,1.905) D31(-13.335,1.905) D32(-14.605,1.905) D33(-15.875,1.905) D34(-17.145,1.905) D35(-18.415,1.905) D36(-19.685,1.905) D37(-20.955,1.905) D38(-22.225,1.905) D39(-23.495,1.905) D40(-24.765,1.905) E1(24.765,0.635) E2(23.495,0.635) E3(22.225,0.635) E4(20.955,0.635) E5(19.685,0.635) E6(18.415,0.635) E7(17.145,0.635) E8(15.875,0.635) E9(14.605,0.635) E10(13.335,0.635) E11(12.065,0.635) E12(10.795,0.635) E13(9.525,0.635) E14(8.255,0.635) E15(6.985,0.635) E16(5.715,0.635) E17(4.445,0.635) E18(3.175,0.635) E19(1.905,0.635) E20(0.635,0.635) E21(-0.635,0.635) E22(-1.905,0.635) E23(-3.175,0.635) E24(-4.445,0.635) E25(-5.715,0.635) E26(-6.985,0.635) E27(-8.255,0.635) E28(-9.525,0.635) E29(-10.795,0.635) E30(-12.065,0.635) E31(-13.335,0.635) E32(-14.605,0.635) E33(-15.875,0.635) E34(-17.145,0.635) E35(-18.415,0.635) E36(-19.685,0.635) E37(-20.955,0.635) E38(-22.225,0.635) E39(-23.495,0.635) E40(-24.765,0.635) F1(24.765,-0.635) F2(23.495,-0.635) F3(22.225,-0.635) F4(20.955,-0.635) F5(19.685,-0.635) F6(18.415,-0.635) F7(17.145,-0.635) F8(15.875,-0.635) F9(14.605,-0.635) F10(13.335,-0.635) F11(12.065,-0.635) F12(10.795,-0.635) F13(9.525,-0.635) F14(8.255,-0.635) F15(6.985,-0.635) F16(5.715,-0.635) F17(4.445,-0.635) F18(3.175,-0.635) F19(1.905,-0.635) F20(0.635,-0.635) F21(-0.635,-0.635) F22(-1.905,-0.635) F23(-3.175,-0.635) F24(-4.445,-0.635) F25(-5.715,-0.635) F26(-6.985,-0.635) F27(-8.255,-0.635) F28(-9.525,-0.635) F29(-10.795,-0.635) F30(-12.065,-0.635) F31(-13.335,-0.635) F32(-14.605,-0.635) F33(-15.875,-0.635) F34(-17.145,-0.635) F35(-18.415,-0.635) F36(-19.685,-0.635) F37(-20.955,-0.635) F38(-22.225,-0.635) F39(-23.495,-0.635) F40(-24.765,-0.635) G1(24.765,-1.905) G2(23.495,-1.905) G3(22.225,-1.905) G4(20.955,-1.905) G5(19.685,-1.905) G6(18.415,-1.905) G7(17.145,-1.905) G8(15.875,-1.905) G9(14.605,-1.905) G10(13.335,-1.905) G11(12.065,-1.905) G12(10.795,-1.905) G13(9.525,-1.905) G14(8.255,-1.905) G15(6.985,-1.905) G16(5.715,-1.905) G17(4.445,-1.905) G18(3.175,-1.905) G19(1.905,-1.905) G20(0.635,-1.905) G21(-0.635,-1.905) G22(-1.905,-1.905) G23(-3.175,-1.905) G24(-4.445,-1.905) G25(-5.715,-1.905) G26(-6.985,-1.905) G27(-8.255,-1.905) G28(-9.525,-1.905) G29(-10.795,-1.905) G30(-12.065,-1.905) G31(-13.335,-1.905) G32(-14.605,-1.905) G33(-15.875,-1.905) G34(-17.145,-1.905) G35(-18.415,-1.905) G36(-19.685,-1.905) G37(-20.955,-1.905) G38(-22.225,-1.905) G39(-23.495,-1.905) G40(-24.765,-1.905) H1(24.765,-3.175) H2(23.495,-3.175) H3(22.225,-3.175) H4(20.955,-3.175) H5(19.685,-3.175) H6(18.415,-3.175) H7(17.145,-3.175) H8(15.875,-3.175) H9(14.605,-3.175) H10(13.335,-3.175) H11(12.065,-3.175) H12(10.795,-3.175) H13(9.525,-3.175) H14(8.255,-3.175) H15(6.985,-3.175) H16(5.715,-3.175) H17(4.445,-3.175) H18(3.175,-3.175) H19(1.905,-3.175) H20(0.635,-3.175) H21(-0.635,-3.175) H22(-1.905,-3.175) H23(-3.175,-3.175) H24(-4.445,-3.175) H25(-5.715,-3.175) H26(-6.985,-3.175) H27(-8.255,-3.175) H28(-9.525,-3.175) H29(-10.795,-3.175) H30(-12.065,-3.175) H31(-13.335,-3.175) H32(-14.605,-3.175) H33(-15.875,-3.175) H34(-17.145,-3.175) H35(-18.415,-3.175) H36(-19.685,-3.175) H37(-20.955,-3.175) H38(-22.225,-3.175) H39(-23.495,-3.175) H40(-24.765,-3.175) J1(24.765,-4.445) J2(23.495,-4.445) J3(22.225,-4.445) J4(20.955,-4.445) J5(19.685,-4.445) J6(18.415,-4.445) J7(17.145,-4.445) J8(15.875,-4.445) J9(14.605,-4.445) J10(13.335,-4.445) J11(12.065,-4.445) J12(10.795,-4.445) J13(9.525,-4.445) J14(8.255,-4.445) J15(6.985,-4.445) J16(5.715,-4.445) J17(4.445,-4.445) J18(3.175,-4.445) J19(1.905,-4.445) J20(0.635,-4.445) J21(-0.635,-4.445) J22(-1.905,-4.445) J23(-3.175,-4.445) J24(-4.445,-4.445) J25(-5.715,-4.445) J26(-6.985,-4.445) J27(-8.255,-4.445) J28(-9.525,-4.445) J29(-10.795,-4.445) J30(-12.065,-4.445) J31(-13.335,-4.445) J32(-14.605,-4.445) J33(-15.875,-4.445) J34(-17.145,-4.445) J35(-18.415,-4.445) J36(-19.685,-4.445) J37(-20.955,-4.445) J38(-22.225,-4.445) J39(-23.495,-4.445) J40(-24.765,-4.445) K1(24.765,-5.715) K2(23.495,-5.715) K3(22.225,-5.715) K4(20.955,-5.715) K5(19.685,-5.715) K6(18.415,-5.715) K7(17.145,-5.715) K8(15.875,-5.715) K9(14.605,-5.715) K10(13.335,-5.715) K11(12.065,-5.715) K12(10.795,-5.715) K13(9.525,-5.715) K14(8.255,-5.715) K15(6.985,-5.715) K16(5.715,-5.715) K17(4.445,-5.715) K18(3.175,-5.715) K19(1.905,-5.715) K20(0.635,-5.715) K21(-0.635,-5.715) K22(-1.905,-5.715) K23(-3.175,-5.715) K24(-4.445,-5.715) K25(-5.715,-5.715) K26(-6.985,-5.715) K27(-8.255,-5.715) K28(-9.525,-5.715) K29(-10.795,-5.715) K30(-12.065,-5.715) K31(-13.335,-5.715) K32(-14.605,-5.715) K33(-15.875,-5.715) K34(-17.145,-5.715) K35(-18.415,-5.715) K36(-19.685,-5.715) K37(-20.955,-5.715) K38(-22.225,-5.715) K39(-23.495,-5.715) K40(-24.765,-5.715)
  round 1.27 hole 1.27 unplated: ""(-27.191,-3.05) ""(27.191,0)
  silkscreen extent -27.89,-7.34 28.78,7.34, body extent -27.89,-7.34 28.78,7.34, height 7.11
SF-1206F500M-2_1206 [mm]
  rrect7% 1.45x1.8 smd paste+0 mask+0.05: 1(-1.475,0) 2(1.475,0)
  silkscreen extent -0.55,-0.9 0.55,0.9, body extent -1.6,-0.8 1.6,0.8, height 1.05
SIL0008D [mm] "SIP, 8-Leads, Body 2.8x3.0mm, Pitch 0.65mm, Thermal Pad 1.9x1.1mm"
  rrect12% 1.04x0.85 on Top Paste: 0(0,-0.525) 0(0,0.525)
  rrect40% 0.6x0.5 smd paste-0.05 mask-0.05: 1(-1.05,0.975) 2(-1.05,0.325) 3(-1.05,-0.325) 4(-1.05,-0.975) 5(1.05,-0.975) 6(1.05,-0.325) 7(1.05,0.325) 8(1.05,0.975)
  round 0.457 hole 0.203 mask+0.05: 9(0,-0.75) 9(0,0) 9(0,0.75)
  rrect17% 1.2x2 smd paste-0.6 mask-0.05: 9(0,0)
  silkscreen extent -1.53,-1.63 1.53,1.63, body extent -1.4,-1.5 1.4,1.5, height 1.53
SMBJ15CA [mil]
  rrect20% 85x107.99 smd: 1(-87.01,0) 2(87.01,0)
  silkscreen extent -125,-79 125,79, body extent -104,-73 104,73, height 89
SOD-123 [mm] "On Semi recommended land pattern"
  rrect20% 0.915x1.22 smd: 1(-1.637,0) 2(1.637,0)
  silkscreen extent -2.74,-1.17 2.03,1.17, body extent -1.93,-0.9 1.93,0.9, height 1.35
SOD-128 [mm] "SMD, 2-Leads, Body 4x2.7mm, Height 1.1mm"
  rrect20% 1.4x2.1 smd paste-0.1: 1(-2.2,0) 2(2.2,0)
  silkscreen extent -3.45,-1.45 2.95,1.45, body extent -2,-1.35 2,1.35, height 1.1
SOT-323 [mm] "Diodes Inc recommended land pattern.  2016-02-24"
  rrect21% 0.6x0.47 smd: 1(-0.95,0.65) 2(-0.95,-0.65) 3(0.95,0)
  silkscreen extent -1.14,-1.22 0.77,1.22, body extent -1.13,-1.13 1.12,1.12, height 1.13
SOT-323-DIO [mm]
  rrect21% 0.9x0.8 smd: 1(-1,0.95) 2(-1,-0.95) 3(1,0)
  silkscreen extent -1.14,-1.52 0.77,1.52, body extent -1.25,-1.5 1.24,1.5, height 1.2
TDFN8 [mm]
  rrect30% 0.75x0.3 smd paste+0 mask+0.05: 1(-1.5,0.75) 2(-1.5,0.25) 3(-1.5,-0.25) 4(-1.5,-0.75) 5(1.478,-0.75) 6(1.478,-0.25) 7(1.478,0.25) 8(1.478,0.75)
  round 0.327 / inner round 0.454 / far side round 0.454 hole 0.2 mask+0.05: 9(-0.5,0) 9(0,0.5) 9(0,0) 9(0,-0.5) 9(0.5,0)
  rrect10% 1.36x1.46 smd paste+0 mask+0.05: 9(0,0)
  silkscreen extent -2.23,0.67 -2.14,0.83, body extent -1.5,-1 1.5,1, height 0.76
TI_Stacked_Overlay_Small [mil]
  silkscreen extent -418,-98 418,98
TSSOP-8 [mm] "TSSOP, 8-Leads, Body 3.1x4.5mm (max), Pitch 0.65mm, IPC Medium Density"
  rrect50% 1.7x0.35 smd: 1(-2.85,0.975) 2(-2.85,0.325) 3(-2.85,-0.325) 4(-2.85,-0.975) 5(2.85,-0.975) 6(2.85,-0.325) 7(2.85,0.325) 8(2.85,0.975)
  silkscreen extent -2.97,-1.55 1.6,1.83, body extent -3.2,-1.55 3.2,1.55, height 1.07
WEEE_Minimum [mil] "WEEElie bin"
  silkscreen extent -95,-172 99,104
XTAL_ABM3 [mm] "Abracon recommended land pattern 12.28.10"
  rect 1.9x2.4 smd: 1(-2.05,0) 2(2.05,0)
  silkscreen extent -2.67,-1.78 2.67,1.78, body extent -2.6,-1.7 2.6,1.7, height 1.3

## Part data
C1 C24 C26 C27 C31 C33 C34 C38 C40 C41 C45 C47 C48 C71 C72 C77 C78 C122: library part capcc09406, "CAP CER 10UF 10V X5R 0402", Manufacturer="KYOCERA AVX", Operating Temperature="-55°C ~ 85°C", Ratings=-, Supplier Part Number 1=478-10052-1-ND, Temperature Coefficient=X5R, Tolerance=±20%, Voltage - Rated=10V
C2: library part capcc02732, "CAP CER 1UF 50V X7R 0603", Manufacturer="KYOCERA AVX", Operating Temperature="-55°C ~ 125°C", Ratings=-, Supplier Part Number 1=478-10073-1-ND, Temperature Coefficient=X7R, Tolerance=±10%, Voltage - Rated=50V
C3 C4: library part capcc03751, "CAP CER 1000PF 50V X7R 0603", Manufacturer="TDK Corporation", Operating Temperature="-55°C ~ 125°C", Ratings=AEC-Q200, Supplier Part Number 1=445-5659-1-ND, Temperature Coefficient=X7R, Tolerance=±10%, Voltage - Rated=50V
C5 C6 C11 C12 C22 C23 C29 C30 C36 C37 C43 C44 C81 C82 C84 C86 C88 C89 C90 C123 C124 C164 C165 C167 C168 C169 C170 C171 C172 C173 C175 C176 C177 C180 C183 C184 C185 C186 C187 C188 C189 C190: library part capcc01263, "CAP CER 0.1UF 25V X5R 0402", Manufacturer="TDK Corporation", Operating Temperature="-55°C ~ 85°C", Ratings=-, Supplier Part Number 1=445-4964-1-ND, Temperature Coefficient=X5R, Tolerance=±10%, Voltage - Rated=25V
C7 C8 C14 C59: library part capcc03515, "CAP CER 10UF 25V X5R 0805", Manufacturer="KYOCERA AVX", Operating Temperature="-55°C ~ 85°C", Ratings=-, Supplier Part Number 1=478-08053D106KAT4ACT-ND, Temperature Coefficient=X5R, Tolerance=±10%, Voltage - Rated=25V
C9 C10 C166 C174 C178: library part capcc03139, "CAP CER 4.7UF 10V X5R 0402", Manufacturer="TDK Corporation", Operating Temperature="-55°C ~ 85°C", Ratings=-, Supplier Part Number 1=445-175214-1-ND, Temperature Coefficient=X5R, Tolerance=±10%, Voltage - Rated=10V
C13: library part capcc04791, "CAP CER 3300PF 50V X7R 0402", Manufacturer="KYOCERA AVX", Operating Temperature="-55°C ~ 125°C", Ratings=AEC-Q200, Supplier Part Number 1=478-04025C332K4T2ACT-ND, Temperature Coefficient=X7R, Tolerance=±10%, Voltage - Rated=50V
C15 C60: library part capcc04225, "CAP CER 2200PF 25V X7R 0402", Manufacturer="KYOCERA AVX", Operating Temperature="-55°C ~ 125°C", Ratings=-, Supplier Part Number 1=478-12619-1-ND, Temperature Coefficient=X7R, Tolerance=±5%, Voltage - Rated=25V
C16 C17 C18 C19 C20 C61 C62 C63 C64 C65: library part capcc03698, "CAP CER 22UF 10V X5R 0805", Manufacturer="KYOCERA AVX", Operating Temperature="-55°C ~ 85°C", Ratings=-, Temperature Coefficient=X5R, Tolerance=±10%, Voltage - Rated=10V
C21 C66: library part capcc05923, "CAP CER 0.022UF 25V X7R 0402", Manufacturer="TDK Corporation", Operating Temperature="-55°C ~ 125°C", Ratings=AEC-Q200, Supplier Part Number 1=445-5609-1-ND, Temperature Coefficient=X7R, Tolerance=±10%, Voltage - Rated=25V
C25 C28 C32 C35 C39 C42 C46 C49 C80 C83 C85 C87 C141 C142 C160 C161: library part capcc02750, "CAP CER 1UF 25V X5R 0402", Manufacturer="TDK Corporation", Operating Temperature="-55°C ~ 85°C", Ratings=-, Supplier Part Number 1=445-9066-1-ND, Temperature Coefficient=X5R, Tolerance=±10%, Voltage - Rated=25V
C50 C53 C54 C55: library part capcc03657, "CAP CER 10UF 10V X5R 0603", Manufacturer="KYOCERA AVX", Operating Temperature="-55°C ~ 85°C", Ratings=-, Supplier Part Number 1=478-10766-1-ND, Temperature Coefficient=X5R, Tolerance=±10%, Voltage - Rated=10V
C51: library part capcc03112, "CAP CER 2.2UF 10V X5R 0402", Manufacturer="TDK Corporation", Operating Temperature="-55°C ~ 85°C", Ratings=-, Supplier Part Number 1=445-7392-1-ND, Temperature Coefficient=X5R, Tolerance=±10%, Voltage - Rated=10V
C52: library part capcc09264, "CAP CER 1UF 10V X5R 0201", Manufacturer="Murata Electronics", Operating Temperature="-55°C ~ 85°C", Ratings=-, Supplier Part Number 1=490-GRM033R61A105ME44DCT-ND, Temperature Coefficient=X5R, Tolerance=±20%, Voltage - Rated=10V
C56 C57 C58 C67: library part capcc06830, "CAP CER 100UF 6.3V X5R 0805", Manufacturer="CAL-CHIP ELECTRONICS, INC.", Operating Temperature="-55°C ~ 85°C", Ratings=-, Supplier Part Number 1=2571-GMC21X5R107M6R3NTTR-ND, Temperature Coefficient=X5R, Tolerance=±20%, Voltage - Rated=6.3V
C92 C101 C104 C105 C106 C107 C108 C109 C111 C120 C134 C139 C153 C158: library part capcc09263, "CAP CER 0.1UF 16V X7R 0201", Manufacturer="Murata Electronics", Operating Temperature="-55°C ~ 125°C", Ratings=-, Supplier Part Number 1=490-GRM033Z71C104KE14DCT-ND, Temperature Coefficient=X7R, Tolerance=±10%, Voltage - Rated=16V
